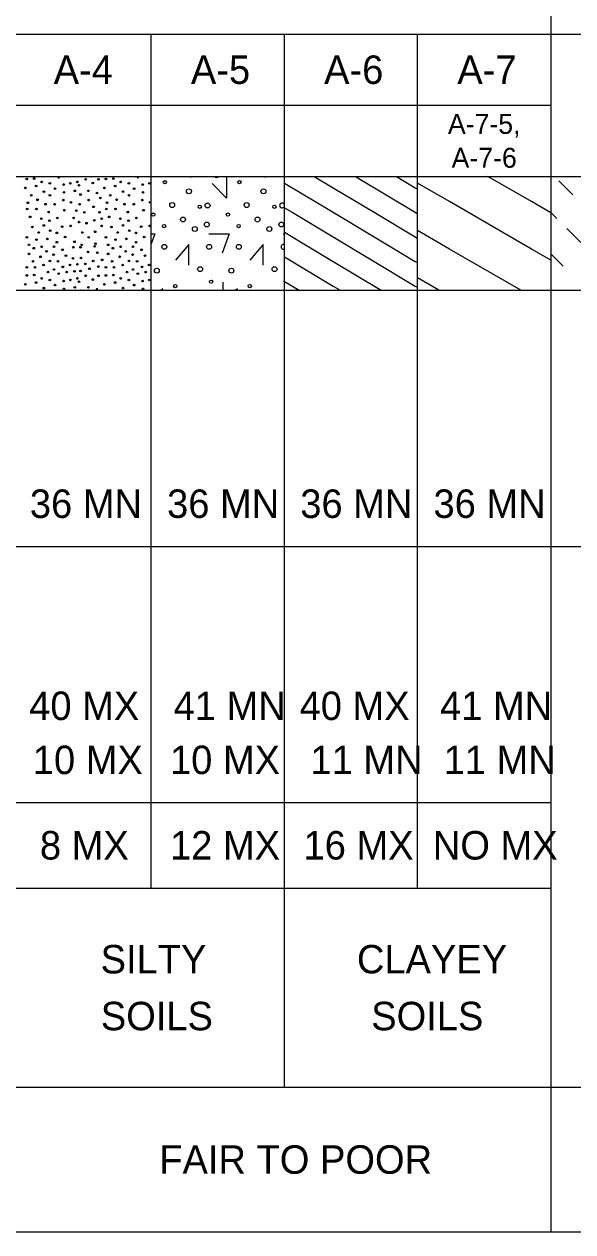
# Model space of a CAD drawing. Extents: x 278618 to 280654, y 171155 to 171855.
# Drawn here: x 280492.58 to 280500.95, y 171593.09 to 171611.5 of the extents above; entities that cross this region are included whole.
import ezdxf

# ---------------------------------------------------------------- set-up
doc = ezdxf.new("R2010")
doc.units = 0
doc.layers.add('Geotech Sheets and Borders Cell', color=7, linetype='Continuous')

msp = doc.modelspace()

# ---------------------------------------------------------------- linework, layer by layer
at = {"layer": 'Geotech Sheets and Borders Cell'}
for p, q in [((280500.609, 171613.515), (280500.609, 171593.093)), ((280474.148, 171611.346), (280511.888, 171611.346)), ((280494.519, 171598.333), (280494.519, 171611.346)), ((280496.549, 171595.296), (280496.549, 171611.346)), ((280498.579, 171598.333), (280498.579, 171611.346)), ((280478.269, 171610.262), (280500.609, 171610.262)), ((280474.148, 171609.177), (280511.888, 171609.177)), ((280496.549, 171609.077), (280497.291, 171608.631)), ((280497.006, 171609.177), (280497.291, 171609.006)), ((280497.291, 171609.006), (280497.916, 171608.631)), ((280497.631, 171609.177), (280498.541, 171608.631)), ((280498.256, 171609.177), (280498.541, 171609.006)), ((280498.541, 171609.006), (280498.579, 171608.984)), ((280499.066, 171608.793), (280498.579, 171609.073)), ((280500.316, 171608.793), (280499.649, 171609.177)), ((280500.943, 171608.899), (280500.731, 171609.112)), ((280496.549, 171608.701), (280496.666, 171608.631)), ((280496.666, 171608.631), (280497.291, 171608.256)), ((280497.291, 171608.631), (280498.541, 171607.881)), ((280497.916, 171608.631), (280498.541, 171608.256)), ((280498.541, 171608.631), (280498.579, 171608.609)), ((280500.316, 171608.071), (280499.066, 171608.793)), ((280500.609, 171608.623), (280500.316, 171608.793)), ((280500.701, 171608.535), (280500.609, 171608.626)), ((280496.549, 171608.327), (280497.291, 171607.881)), ((280499.066, 171608.071), (280498.579, 171608.352)), ((280501.065, 171608.171), (280500.852, 171608.383)), ((280497.291, 171608.256), (280498.541, 171607.506)), ((280498.541, 171608.256), (280498.579, 171608.234)), ((280496.549, 171607.952), (280497.291, 171607.506)), ((280500.154, 171607.442), (280499.066, 171608.071)), ((280500.609, 171607.901), (280500.316, 171608.071)), ((280500.796, 171607.811), (280500.609, 171607.997)), ((280497.291, 171607.881), (280498.023, 171607.442)), ((280498.541, 171607.881), (280498.579, 171607.859)), ((280496.549, 171607.577), (280496.773, 171607.442)), ((280498.904, 171607.442), (280498.579, 171607.63)), ((280474.148, 171607.442), (280511.888, 171607.442)), ((280497.291, 171607.506), (280497.398, 171607.442)), ((280498.541, 171607.506), (280498.579, 171607.484)), ((280474.148, 171603.538), (280511.888, 171603.538)), ((280474.148, 171599.634), (280500.609, 171599.634)), ((280474.148, 171598.333), (280500.609, 171598.333)), ((280474.148, 171595.296), (280511.888, 171595.296)), ((280474.148, 171593.093), (280511.888, 171593.093))]:
    msp.add_line(p, q, dxfattribs=at)
for points in [[(280495.125, 171609.159), (280495.125, 171609.177)], [(280495.669, 171609.159), (280495.669, 171608.847), (280495.448, 171609.068)], [(280496.26, 171609.159), (280496.26, 171609.177)], [(280494.519, 171608.302), (280494.575, 171608.302), (280494.519, 171608.15)], [(280495.398, 171608.302), (280495.71, 171608.302), (280495.603, 171608.008)], [(280496.533, 171608.302), (280496.549, 171608.302)], [(280495.091, 171607.826), (280495.091, 171608.138), (280494.89, 171607.899)], [(280496.226, 171607.826), (280496.226, 171608.138), (280496.025, 171607.899)], [(280495.613, 171607.564), (280495.613, 171607.442)], [(280494.668, 171607.442), (280494.698, 171607.472)], [(280495.804, 171607.442), (280495.834, 171607.472)]]:
    msp.add_lwpolyline(points, dxfattribs=at)
for centre, radius in [((280492.601, 171609.003), 0.0125), ((280492.624, 171609.139), 0.0125), ((280492.737, 171609.145), 0.0125), ((280492.766, 171609.031), 0.0125), ((280492.851, 171609.094), 0.0125), ((280492.975, 171609.071), 0.0125), ((280493.055, 171608.992), 0.0125), ((280493.186, 171609.054), 0.0125), ((280493.288, 171609.071), 0.0125), ((280493.395, 171609.094), 0.0125), ((280493.42, 171609.043), 0.0125), ((280493.522, 171609.134), 0.0125), ((280493.63, 171609.077), 0.0125), ((280493.716, 171609.134), 0.0125), ((280493.806, 171609.003), 0.0125), ((280493.829, 171609.139), 0.0125), ((280493.942, 171609.145), 0.0125), ((280493.971, 171609.031), 0.0125), ((280494.056, 171609.094), 0.0125), ((280494.18, 171609.071), 0.0125), ((280494.26, 171608.992), 0.0125), ((280494.391, 171609.054), 0.0125), ((280494.493, 171609.071), 0.0125), ((280494.728, 171609.09), 0.025), ((280495.864, 171609.09), 0.025), ((280492.692, 171608.89), 0.0125), ((280492.788, 171608.822), 0.0125), ((280492.885, 171608.946), 0.0125), ((280492.976, 171608.89), 0.0125), ((280493.18, 171608.816), 0.0125), ((280493.191, 171608.935), 0.0125), ((280493.356, 171608.958), 0.0125), ((280493.443, 171608.901), 0.0125), ((280493.562, 171608.958), 0.0125), ((280493.568, 171608.816), 0.0125), ((280493.693, 171608.924), 0.0125), ((280493.744, 171608.85), 0.0125), ((280493.897, 171608.89), 0.0125), ((280493.993, 171608.822), 0.0125), ((280494.09, 171608.946), 0.0125), ((280494.181, 171608.89), 0.0125), ((280494.385, 171608.816), 0.0125), ((280494.396, 171608.935), 0.0125), ((280495.095, 171608.951), 0.0375), ((280496.23, 171608.951), 0.0375), ((280492.63, 171608.68), 0.0125), ((280492.641, 171608.776), 0.0125), ((280492.771, 171608.68), 0.0125), ((280492.908, 171608.754), 0.0125), ((280492.958, 171608.634), 0.0125), ((280493.05, 171608.754), 0.0125), ((280493.197, 171608.663), 0.0125), ((280493.299, 171608.782), 0.0125), ((280493.378, 171608.657), 0.0125), ((280493.431, 171608.754), 0.0125), ((280493.5, 171608.629), 0.0125), ((280493.641, 171608.714), 0.0125), ((280493.732, 171608.629), 0.0125), ((280493.835, 171608.68), 0.0125), ((280493.846, 171608.776), 0.0125), ((280493.976, 171608.68), 0.0125), ((280494.113, 171608.754), 0.0125), ((280494.163, 171608.634), 0.0125), ((280494.255, 171608.754), 0.0125), ((280494.402, 171608.663), 0.0125), ((280494.504, 171608.782), 0.0125), ((280494.839, 171608.741), 0.0375), ((280495.261, 171608.715), 0.025), ((280495.379, 171608.735), 0.0375), ((280495.975, 171608.741), 0.0375), ((280496.397, 171608.715), 0.025), ((280492.675, 171608.561), 0.0125), ((280492.845, 171608.533), 0.0125), ((280492.97, 171608.504), 0.0125), ((280493.089, 171608.544), 0.0125), ((280493.339, 171608.544), 0.0125), ((280493.42, 171608.481), 0.0125), ((280493.534, 171608.464), 0.0125), ((280493.653, 171608.509), 0.0125), ((280493.766, 171608.533), 0.0125), ((280493.88, 171608.561), 0.0125), ((280494.05, 171608.533), 0.0125), ((280494.175, 171608.504), 0.0125), ((280494.294, 171608.544), 0.0125), ((280494.552, 171608.597), 0.025), ((280494.717, 171608.42), 0.025), ((280495.004, 171608.52), 0.0375), ((280495.368, 171608.445), 0.0375), ((280495.688, 171608.597), 0.025), ((280495.853, 171608.42), 0.025), ((280496.14, 171608.52), 0.0375), ((280496.503, 171608.445), 0.0375), ((280492.624, 171608.249), 0.0125), ((280492.709, 171608.408), 0.0125), ((280492.805, 171608.323), 0.0125), ((280492.885, 171608.43), 0.0125), ((280492.981, 171608.351), 0.0125), ((280493.083, 171608.317), 0.0125), ((280493.163, 171608.413), 0.0125), ((280493.208, 171608.254), 0.0125), ((280493.293, 171608.424), 0.0125), ((280493.471, 171608.323), 0.0125), ((280493.568, 171608.249), 0.0125), ((280493.665, 171608.334), 0.0125), ((280493.766, 171608.424), 0.0125), ((280493.829, 171608.249), 0.0125), ((280493.914, 171608.408), 0.0125), ((280494.01, 171608.323), 0.0125), ((280494.09, 171608.43), 0.0125), ((280494.186, 171608.351), 0.0125), ((280494.288, 171608.317), 0.0125), ((280494.368, 171608.413), 0.0125), ((280494.413, 171608.254), 0.0125), ((280494.498, 171608.424), 0.0125), ((280495.185, 171608.377), 0.0375), ((280496.321, 171608.377), 0.0375), ((280492.658, 171608.135), 0.0125), ((280492.731, 171608.083), 0.0125), ((280492.771, 171608.214), 0.0125), ((280492.851, 171608.105), 0.0125), ((280492.936, 171608.226), 0.0125), ((280493.038, 171608.105), 0.0125), ((280493.083, 171608.175), 0.0125), ((280493.333, 171608.099), 0.0125), ((280493.35, 171608.181), 0.0125), ((280493.443, 171608.099), 0.0125), ((280493.46, 171608.135), 0.0125), ((280493.658, 171608.111), 0.0125), ((280493.67, 171608.152), 0.0125), ((280493.863, 171608.135), 0.0125), ((280493.936, 171608.083), 0.0125), ((280493.976, 171608.214), 0.0125), ((280494.056, 171608.105), 0.0125), ((280494.141, 171608.226), 0.0125), ((280494.243, 171608.105), 0.0125), ((280494.288, 171608.175), 0.0125), ((280494.72, 171608.105), 0.0375), ((280495.402, 171608.105), 0.0375), ((280495.856, 171608.105), 0.0375), ((280492.658, 171607.997), 0.0125), ((280492.72, 171607.884), 0.0125), ((280492.834, 171607.953), 0.0125), ((280492.925, 171608.037), 0.0125), ((280492.976, 171607.889), 0.0125), ((280493.032, 171607.986), 0.0125), ((280493.1, 171607.884), 0.0125), ((280493.168, 171608.059), 0.0125), ((280493.22, 171607.969), 0.0125), ((280493.327, 171607.929), 0.0125), ((280493.449, 171607.935), 0.0125), ((280493.556, 171608.026), 0.0125), ((280493.636, 171607.889), 0.0125), ((280493.698, 171608.014), 0.0125), ((280493.772, 171607.906), 0.0125), ((280493.863, 171607.997), 0.0125), ((280493.925, 171607.884), 0.0125), ((280494.039, 171607.953), 0.0125), ((280494.13, 171608.037), 0.0125), ((280494.181, 171607.889), 0.0125), ((280494.237, 171607.986), 0.0125), ((280494.305, 171607.884), 0.0125), ((280494.373, 171608.059), 0.0125), ((280494.425, 171607.969), 0.0125), ((280492.624, 171607.793), 0.0125), ((280492.749, 171607.793), 0.0125), ((280492.879, 171607.827), 0.0125), ((280492.947, 171607.719), 0.0125), ((280493.038, 171607.759), 0.0125), ((280493.111, 171607.696), 0.0125), ((280493.174, 171607.799), 0.0125), ((280493.231, 171607.719), 0.0125), ((280493.283, 171607.828), 0.0125), ((280493.35, 171607.731), 0.0125), ((280493.395, 171607.838), 0.0125), ((280493.443, 171607.736), 0.0125), ((280493.516, 171607.844), 0.0125), ((280493.579, 171607.77), 0.0125), ((280493.715, 171607.804), 0.0125), ((280493.829, 171607.793), 0.0125), ((280493.954, 171607.793), 0.0125), ((280494.084, 171607.827), 0.0125), ((280494.152, 171607.719), 0.0125), ((280494.243, 171607.759), 0.0125), ((280494.316, 171607.696), 0.0125), ((280494.379, 171607.799), 0.0125), ((280494.436, 171607.719), 0.0125), ((280494.488, 171607.828), 0.0125), ((280494.606, 171607.742), 0.0375), ((280495.265, 171607.764), 0.0375), ((280495.742, 171607.742), 0.0375), ((280496.4, 171607.764), 0.0375), ((280492.601, 171607.532), 0.0125), ((280492.624, 171607.668), 0.0125), ((280492.737, 171607.674), 0.0125), ((280492.766, 171607.56), 0.0125), ((280492.851, 171607.623), 0.0125), ((280492.975, 171607.599), 0.0125), ((280493.055, 171607.521), 0.0125), ((280493.186, 171607.583), 0.0125), ((280493.288, 171607.6), 0.0125), ((280493.395, 171607.623), 0.0125), ((280493.42, 171607.572), 0.0125), ((280493.522, 171607.663), 0.0125), ((280493.63, 171607.606), 0.0125), ((280493.716, 171607.663), 0.0125), ((280493.806, 171607.532), 0.0125), ((280493.829, 171607.668), 0.0125), ((280493.942, 171607.674), 0.0125), ((280493.971, 171607.56), 0.0125), ((280494.056, 171607.623), 0.0125), ((280494.18, 171607.599), 0.0125), ((280494.26, 171607.521), 0.0125), ((280494.391, 171607.583), 0.0125), ((280494.493, 171607.6), 0.0125), ((280494.887, 171607.506), 0.025), ((280495.433, 171607.574), 0.025), ((280496.023, 171607.506), 0.025), ((280492.885, 171607.475), 0.0125), ((280493.191, 171607.464), 0.0125), ((280493.356, 171607.486), 0.0125), ((280493.562, 171607.486), 0.0125), ((280494.09, 171607.475), 0.0125), ((280494.396, 171607.464), 0.0125)]:
    msp.add_circle(centre, radius, dxfattribs=at)
for centre, radius, start, end in [((280493.111, 171609.168), 0.0125, 128.4735, 51.5265), ((280494.316, 171609.168), 0.0125, 128.4735, 51.5265), ((280495.515, 171609.2), 0.0375, 217.8115, 322.1885), ((280496.515, 171608.735), 0.0375, 22.8613, 337.1387), ((280496.538, 171608.105), 0.0375, 72.255, 287.745), ((280496.568, 171607.574), 0.025, 140.1592, 219.8408), ((280493.443, 171607.43), 0.0125, 79.3017, 100.6983), ((280493.693, 171607.453), 0.0125, 305.1764, 234.8236)]:
    msp.add_arc(centre, radius, start, end, dxfattribs=at)

# ---------------------------------------------------------------- texts
for s, height, p in [('A-4', 0.4338, (280493.034, 171610.587)), ('A-5', 0.4338, (280495.125, 171610.587)), ('A-6', 0.4338, (280497.155, 171610.587)), ('A-7', 0.4338, (280499.185, 171610.587)), ('A-7-5,', 0.3037, (280499.042, 171609.826)), ('A-7-6', 0.3037, (280499.098, 171609.31)), ('36 MN', 0.4338, (280492.671, 171603.973)), ('36 MN', 0.4338, (280494.762, 171603.973)), ('36 MN', 0.4338, (280496.792, 171603.973)), ('36 MN', 0.4338, (280498.822, 171603.973)), ('40 MX', 0.4338, (280492.661, 171600.893)), ('41 MN', 0.4338, (280494.862, 171600.893)), ('40 MX', 0.4338, (280496.782, 171600.893)), ('41 MN', 0.4338, (280498.922, 171600.893)), ('10 MX', 0.4338, (280492.716, 171600.069)), ('10 MX', 0.4338, (280494.807, 171600.069)), ('11 MN', 0.4338, (280496.947, 171600.069)), ('11 MN', 0.4338, (280498.977, 171600.069)), ('8 MX', 0.4338, (280492.824, 171598.767)), ('12 MX', 0.4338, (280494.807, 171598.767)), ('16 MX', 0.4338, (280496.842, 171598.767)), ('NO MX', 0.4338, (280498.812, 171598.767)), ('SILTY', 0.4338, (280493.749, 171597.031)), ('CLAYEY', 0.4338, (280497.655, 171597.031)), ('SOILS', 0.4338, (280493.752, 171596.165)), ('SOILS', 0.4338, (280497.873, 171596.165)), ('FAIR TO POOR', 0.43381, (280494.643, 171593.978))]:
    msp.add_text(s, height=height, dxfattribs=at).set_placement(p)

doc.saveas('drawing.dxf')
